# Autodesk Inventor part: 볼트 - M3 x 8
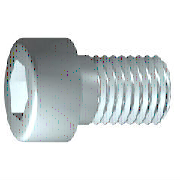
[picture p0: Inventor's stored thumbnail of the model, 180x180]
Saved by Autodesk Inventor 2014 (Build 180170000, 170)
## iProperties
IsCustomPart: 0
Created: 2012-02
Part Number: 볼트 - M3 x 8
Material: 스테인리스강
Description: 6각 소켓 머리 캡 나사
Document SubType Name: Modeling
Standard: ISO 4762
Designer: mduedu
Standard Revision: Fourth edition 2004-03-01
Standards Organization: ISO
Language: ko-KR
Size Designation: M3 x 8
Categories: <MemberInstance><Categories><Category DisplayName="조임쇠" InternalName="e4da775c-781d-43d5-af7c-5136215cf5a6" Mnemonic="FSTN"><Category DisplayName="볼트" InternalN
Density: 8.08 g/cm^3
Mass: 0.95587 g
Surface Area: 1.83001 cm^2
Volume: 0.118301 cm^3
Appearance: 반광택
Author: mduedu
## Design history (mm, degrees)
sketch "스케치1"
  geometry: L1 (-0.867, 0)-(8, 0); L2 (8, 0)-(8, 1.5); L3 (8, 1.5)-(1.25, 1.5); L4 (1.25, 1.5)-(0.943, 1.5); L5 (0.943, 1.5)-(0, 1.5); L6 (0, 1.5)-(0, 2.75); L7 (0, 2.75)-(-3, 2.75); L8 (-3, 2.75)-(-3, 1.443); L9 (-3, 1.443)-(-1.7, 1.443); L10 (-1.7, 1.443)-(-0.867, 0); L11 (-5.2, 0)-(10.2, 0) reference; L12 (0, -0.55)-(0, 3.3) reference; L13 (1.25, 1.5)-(0, 1.5)
  constraints: 22 end point, 6 parallel, 2 collinear, 2 perpendicular, 1 horizontal, 1 point on line
  dimensions: "d1" = 6.75 distance from line of L3.end L2 (= GEL); "d2" = 0.30683 distance of L4.end L3.end (computed from GAL); "d3" = 3 distance between parallel lines of L8 L6 (= KOH); "d4" = 1.3 distance of L8.end L9.end (= INTI); "d5" = 60 deg angle of L10 L1; "d6" = 3 diameter of L3 L1 (= GD); "d7" = 3 diameter of L5 L1 (= BDM); "d8" = 2.88675 diameter of L9 L1 (= 1.1547 x SW); "d9" = 5.5 diameter of L7 L1 (= KOD); "d26" = 8 distance between parallel lines of L12 L2 (= NLG)
revolve "본체" sketch "스케치1" stored, may be unused: angle "d10" = 90 deg
sketch "스케치2"
  geometry: L1 (0, -3.85)-(0, 3.85) reference; L2 (-3.85, 0)-(3.85, 0) reference; L3 (1.443, 0)-(0.722, -1.25); L4 (0.722, -1.25)-(-0.722, -1.25); L5 (-0.722, -1.25)-(-1.443, 0); L6 (-1.443, 0)-(-0.722, 1.25); L7 (-0.722, 1.25)-(0.722, 1.25); L8 (0.722, 1.25)-(1.443, 0); 2 further points
  constraints: 12 end point, 1 coincident, 1 horizontal alignment, 1 point on line, 12 other
extrude "슬롯" join sketch "스케치2" stored distance "d11" = 10; taper "d12" = 0 deg
workplane "Work Plane1"
fillet "Fillet2" dims "d30" = 0.1 (= R)
body "Solid1"
fillet "모깎기1" dims "d17" = 0.3 (= RR)
feature "스레드" dims "d13" = 6.75 (= GEL), "d14" = 0
chamfer "모따기1" distance "d15" = 0.30673 (= -0.5 x SPD + 0.5 x GD); stored, may be unused: second distance "d16" = 0.30673 (= GUL), angle "d27" = 45 deg
other parameters: "GD" = 3 [user parameter; used in 2 equation terms], "NLG" = 8 [user parameter; used in 1 equation term], "GEL" = 6.75 [user parameter; used in 2 equation terms], "KOD" = 5.5 [user parameter; used in 1 equation term], "KOH" = 3 [user parameter; used in 1 equation term], "INTI" = 1.3 [user parameter; used in 1 equation term], "GAL" = 0.30673 (= 0.61345 x PTC) [user parameter; used in 1 equation term], "GUL" = 0.30673 (= 0.61345 x PTC) [user parameter; used in 1 equation term], "BDM" = 3 (= NND) [user parameter; used in 1 equation term], "SW" = 2.5 [user parameter; used in 2 equation terms], "RR" = 0.3 [user parameter; used in 1 equation term], "SPD" = 2.38655 (= NND - 1.2269 x PTC) [user parameter; used in 1 equation term], "d19" = 0, "d28" = 0, "d29" = 0, "R" = 0.1 [user parameter; used in 1 equation term], "TOA" = 30 deg [user parameter], "GD1" = 2.38655 (= THREADDIA - 1.2269 x PTC) [user parameter], "THREADDIA" = 3 [user parameter; used in 1 equation term], "FAWI" = 45 deg [user parameter], "PTC" = 0.5 [user parameter; used in 5 equation terms], "NND" = 3 [user parameter; used in 2 equation terms], "E0" = 2.8875 (= 1.155 x SW) [user parameter]
